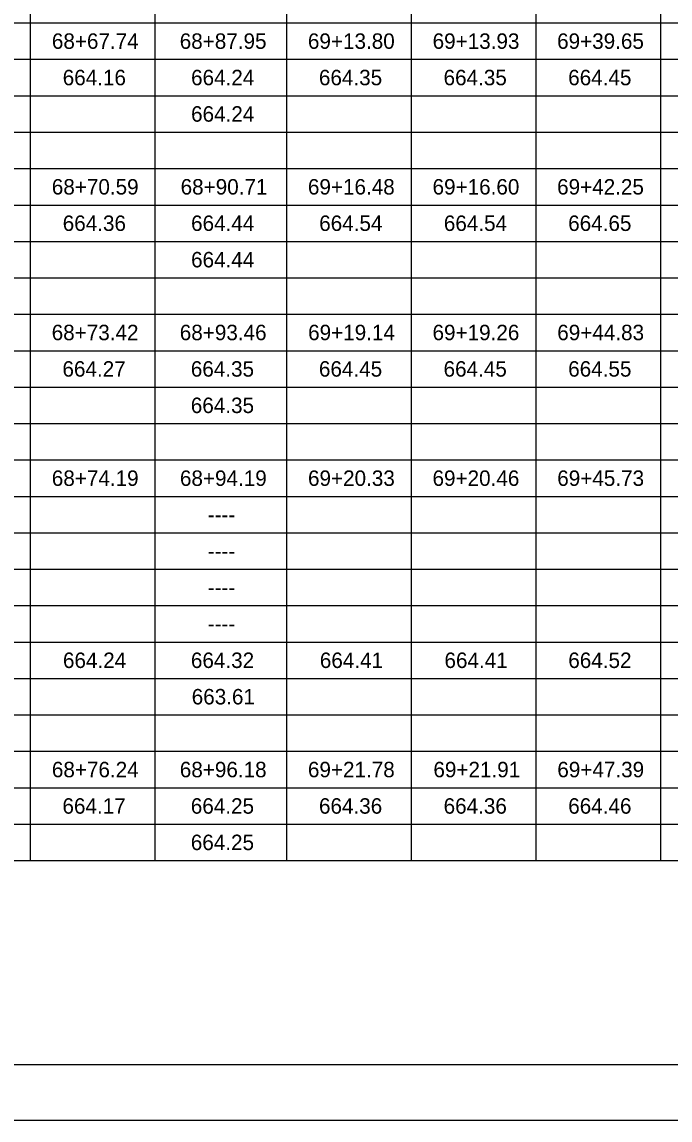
# Model space of a CAD drawing. Extents: x 0 to 34, y 0 to 22.
# Drawn here: x 19.08 to 24.95, y 0 to 9.94 of the extents above; entities that cross this region are included whole.
import ezdxf

# ---------------------------------------------------------------- set-up
doc = ezdxf.new("R2010")
doc.units = 0
for name, color, linetype in [('SH_Border', 7, 'Continuous'), ('SH_Cut_Line', 7, 'Continuous'), ('SH_Text', 7, 'Continuous')]:
    doc.layers.add(name, color=color, linetype=linetype)

msp = doc.modelspace()

# ---------------------------------------------------------------- linework, layer by layer
at = {"layer": 'SH_Border'}
msp.add_lwpolyline([(1.5, 21.5), (33.5, 21.5), (33.5, 0.5), (1.5, 0.5)], close=True, dxfattribs=at)
at = {"layer": 'SH_Cut_Line'}
msp.add_lwpolyline([(0, 0), (34, 0), (34, 22), (0, 22)], close=True, dxfattribs=at)
at = {"layer": 'SH_Text'}
for p, q in [((19.1585, 20.0008), (19.1585, 2.3487)), ((20.2871, 20.0008), (20.2871, 2.3487)), ((21.4792, 20.0008), (21.4792, 2.3487)), ((22.6078, 20.0008), (22.6078, 2.3487)), ((23.7364, 20.0008), (23.7364, 2.3487)), ((24.865, 20.0008), (24.865, 2.3487)), ((2.7998, 9.932), (30.5716, 9.932)), ((4.1947, 9.6023), (30.5716, 9.6023)), ((4.1947, 9.2726), (30.5716, 9.2726)), ((2.7998, 8.9429), (30.5716, 8.9429)), ((2.7998, 8.6131), (30.5716, 8.6131)), ((4.1947, 8.2834), (30.5716, 8.2834)), ((4.1947, 7.9537), (30.5716, 7.9537)), ((2.7998, 7.624), (30.5716, 7.624)), ((2.7998, 7.2943), (30.5716, 7.2943)), ((4.1947, 6.9646), (30.5716, 6.9646)), ((4.1947, 6.6349), (30.5716, 6.6349)), ((2.7998, 6.3052), (30.5716, 6.3052)), ((2.7998, 5.9755), (30.5716, 5.9755)), ((4.1947, 5.6458), (30.5716, 5.6458)), ((4.1947, 5.316), (30.5716, 5.316)), ((4.1947, 4.9863), (30.5716, 4.9863)), ((4.1947, 4.6566), (30.5716, 4.6566)), ((4.1947, 4.3269), (30.5716, 4.3269)), ((4.1947, 3.9972), (30.5716, 3.9972)), ((2.7998, 3.6675), (30.5716, 3.6675)), ((2.7998, 3.3378), (30.5716, 3.3378)), ((4.1947, 3.0081), (30.5716, 3.0081)), ((4.1947, 2.6784), (30.5716, 2.6784)), ((2.7998, 2.3487), (30.5716, 2.3487))]:
    msp.add_line(p, q, dxfattribs=at)

# ---------------------------------------------------------------- texts
for s, p in [('68+67.74', (19.3545, 9.6971)), ('68+87.95', (20.5123, 9.6971)), ('69+13.80', (21.6732, 9.6971)), ('69+13.93', (22.8026, 9.6971)), ('69+39.65', (23.9299, 9.6971)), ('664.16', (19.4527, 9.3674)), ('664.24', (20.6151, 9.3674)), ('664.35', (21.7729, 9.3674)), ('664.35', (22.9016, 9.3674)), ('664.45', (24.0302, 9.3674)), ('664.24', (20.6151, 9.0377)), ('68+70.59', (19.3538, 8.3783)), ('68+90.71', (20.5205, 8.3783)), ('69+16.48', (21.6733, 8.3783)), ('69+16.60', (22.8019, 8.3783)), ('69+42.25', (23.9299, 8.3783)), ('664.36', (19.4527, 8.0486)), ('664.44', (20.6151, 8.0486)), ('664.54', (21.7754, 8.0486)), ('664.54', (22.9041, 8.0486)), ('664.65', (24.0302, 8.0486)), ('664.44', (20.6151, 7.7189)), ('68+73.42', (19.3529, 7.0595)), ('68+93.46', (20.5127, 7.0595)), ('69+19.14', (21.6751, 7.0595)), ('69+19.26', (22.8017, 7.0595)), ('69+44.83', (23.9312, 7.0595)), ('664.27', (19.4503, 6.7297)), ('664.35', (20.6126, 6.7297)), ('664.45', (21.7729, 6.7297)), ('664.45', (22.9016, 6.7297)), ('664.55', (24.0302, 6.7297)), ('664.35', (20.6126, 6.4)), ('68+74.19', (19.3538, 5.7406)), ('68+94.19', (20.5142, 5.7406)), ('69+20.33', (21.674, 5.7406)), ('69+20.46', (22.8017, 5.7406)), ('69+45.73', (23.9312, 5.7406)), ('----', (20.7658, 5.4109)), ('----', (20.7658, 5.0812)), ('----', (20.7658, 4.7515)), ('----', (20.7658, 4.4218)), ('664.24', (19.4548, 4.0921)), ('664.32', (20.6135, 4.0921)), ('664.41', (21.7811, 4.0921)), ('664.41', (22.9098, 4.0921)), ('664.52', (24.0311, 4.0921)), ('663.61', (20.6208, 3.7624)), ('68+76.24', (19.3545, 3.1029)), ('68+96.18', (20.513, 3.1029)), ('69+21.78', (21.6733, 3.1029)), ('69+21.91', (22.8095, 3.1029)), ('69+47.39', (23.9317, 3.1029)), ('664.17', (19.4503, 2.7732)), ('664.25', (20.6126, 2.7732)), ('664.36', (21.7734, 2.7732)), ('664.36', (22.902, 2.7732)), ('664.46', (24.0306, 2.7732)), ('664.25', (20.6126, 2.4435))]:
    msp.add_text(s, height=0.14, dxfattribs=at).set_placement(p)

doc.saveas('drawing.dxf')
